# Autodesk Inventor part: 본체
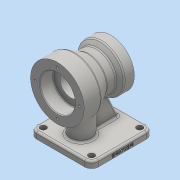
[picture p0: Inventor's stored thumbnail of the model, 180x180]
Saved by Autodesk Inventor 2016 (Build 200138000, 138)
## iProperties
Created: 2019-01
Part Number: 본체
Material: Generic
Document SubType Name: Modeling
Designer: 2-PC10
Density: 1 g/cm^3
Appearance: Default
Author: 2-PC10
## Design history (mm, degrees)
sketch "스케치1"
  geometry: L1 (-46, -46)-(46, -46); L2 (46, -46)-(46, 46); L3 (46, 46)-(-46, 46); L4 (-46, 46)-(-46, -46); L5 (-46, -46)-(46, 46); L6 (46, -46)-(-46, 46); 1 further point
  constraints: 12 end point, 2 midpoint, 2 parallel, 1 horizontal, 1 perpendicular
  dimensions: "d0" = 92 distance of L3.end L2.end; "d1" = 92 distance of L2.end L1.end
extrude "돌출1" new body sketch "스케치1" distance "d2" = 10; taper "d3" = 0 deg
sketch "스케치2"
  geometry: L1 (-51, 80)-(-51, 120); L2 (-51, 120)-(-26, 120); L3 (-26, 120)-(-5.215, 108); L4 (-5.215, 108)-(8.126, 108); L5 (14, 115)-(29, 115); L6 (29, 115)-(29, 80); L7 (29, 80)-(-51, 80); L8 (-46, 0)-(46, 0) reference; L9 (-46, 0)-(-46, 10) reference; L10 (14, 115)-(8.126, 108); 1 further point
  constraints: 16 end point, 3 perpendicular, 2 parallel, 1 vertical
  dimensions: "d4" = 25 distance of L1.end L2.end; "d7" = 80 diameter of L2 L7; "d8" = 56 diameter of L4 L7; "d9" = 70 diameter of L5 L7; "d10" = 80 distance between parallel lines of L8 L7; "d11" = 5 distance between parallel lines of L9 L1; "d12" = 30 deg angle of L4 L3; "d13" = 50 deg angle of L4 L10; "d14" = 15 distance of L5.start L5.end; "d15" = 80 distance between parallel lines of L6 L1
revolve "회전1" sketch "스케치2" stored, may be unused: angle "d16" = 90 deg
sketch "스케치3"
  geometry: L1 (-46, -46)-(46, -46) reference; C1 r 16 at (0, -16); 1 further point
  constraints: 1 centre point, 1 vertical alignment
  dimensions: "d17" = 16 radius of C1; "d18" = 30 distance from line of C1.centre L1
extrude "돌출2" join sketch "스케치3" stored distance "d19" = 10; taper "d20" = 0 deg
sketch "스케치4"
  geometry: L1 (21.486, 41.126)-(36, 10); L2 (46, 0)-(46, 10) reference; L3 (-46, 10)-(46, 10) reference; 1 further point
  constraints: 2 end point, 1 point on line
  dimensions: "d21" = 25 deg angle of L2 L1; "d22" = 10 distance from line of L2 L1.end
feature "리브1" sketch "스케치4" dims "d23" = 1, "d24" = 10, "d25" = 0, "d26" = 0, "d27" = 1, "d28" = 1
sketch "스케치5"
  geometry: L1 (-51, 106)-(-31, 106); L2 (-31, 106)-(-31, 96); L3 (-31, 96)-(12, 96); L4 (12, 96)-(12, 100); L5 (12, 100)-(29, 100); L6 (29, 100)-(29, 80); L7 (29, 80)-(-51, 80); L8 (-51, 80)-(-51, 106); L9 (-51, 40)-(-51, 120) reference; L10 (29, 45)-(29, 115) reference; L11 (46, 0)-(-46, 0) reference; 1 further point
  constraints: 16 end point, 7 perpendicular, 2 collinear, 1 horizontal
  dimensions: "d29" = 52 diameter of L1 L7; "d30" = 32 diameter of L3 L7; "d31" = 40 diameter of L5 L7; "d32" = 80 distance between parallel lines of L11 L7; "d33" = 20 distance of L1.start L1.end; "d34" = 17 distance of L4.end L5.end
revolve "회전2" sketch "스케치5" stored, may be unused: angle "d35" = 90 deg
sketch "스케치6" dims "d36" = 66
  geometry: C1 r 40 at (0, 0) reference; 3 further points
  constraints: 2 vertical alignment, 3 other
hole "구멍1" sketch "스케치6" at (0, 33) diameter "d37" = 3.242; stored, may be unused: countersink angle "d41" = 90 deg, drill point angle "d43" = 118 deg; dims "d38" = 9, "d39" = 4, "d40" = 2, "d42" = 11
sketch "스케치7" dims "d47" = 55
  geometry: C1 r 35 at (0, 0) reference; 3 further points
  constraints: 2 vertical alignment, 3 other
hole "구멍2" sketch "스케치7" at (0, -27.5) diameter "d48" = 3.242; stored, may be unused: countersink angle "d52" = 90 deg, drill point angle "d54" = 118 deg; dims "d49" = 9, "d50" = 4, "d51" = 2, "d53" = 11
fillet "모깎기1" dims "d58" = 1
fillet "모깎기2" dims "d59" = 0.6
fillet "모깎기3" dims "d60" = 3
fillet "모깎기4" dims "d61" = 3
fillet "모깎기5" dims "d62" = 3
fillet "모깎기6" dims "d63" = 3
fillet "모깎기7" dims "d64" = 10
fillet "모깎기8" dims "d65" = 3
hole "구멍3" diameter "d68" = 9; stored, may be unused: countersink angle "d72" = 90 deg, drill point angle "d74" = 0 deg; dims "d66" = 10, "d67" = 10, "d69" = 9, "d70" = 4, "d71" = 2, "d73" = 11
chamfer "모따기1" distance "d81" = 1; stored, may be unused: second distance "d82" = 2, angle "d83" = 45 deg
sketch "스케치8"
  geometry: L1 (-7.5, 18.5)-(-7.5, 53.5); L2 (-7.5, 53.5)-(-0.5, 53.5); L3 (-0.5, 53.5)-(-0.5, 18.5); L4 (-0.5, 18.5)-(-7.5, 18.5); L5 (-4, 18.5)-(-4, 53.5); L6 (-7.5, 36)-(-0.5, 36); L7 (-7, -10)-(0, -10) reference; L8 (0, 0)-(0, 72) reference; 1 further point
  constraints: 4 end point, 4 midpoint, 2 other
  dimensions: "d84" = 46 distance between parallel lines of L6 L7; "d85" = 4 distance between parallel lines of L8 L5; "d86" = 35 distance of L1.start L1.end; "d87" = 7 distance of L1.end L2.end
feature "엠보싱1" sketch "스케치8" dims "d0" = 92, "d1" = 92, "d88" = 0.5, "d89" = 0
node "솔리드1"
pattern_circular "원형 패턴1" dims angle "d45" = 360 deg
pattern_circular "원형 패턴2" dims angle "d56" = 360 deg
pattern_linear "직사각형 패턴1" dims "d77" = 72, "d80" = 72
